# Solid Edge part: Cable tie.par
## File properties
Author: conerly
Template: Normal.par
Last saved by: jccrumbl
Revision: 38
Application: Solid Edge
Density: 1024.000 kg/m^3
Accuracy: 0.990
Material: ABS Plastic, high impact
Face Style: Red
Fill Style: ANSI34(Plastic)
Virtual Style: Red (Shiny)
Coef. of Thermal Exp: 9e-05
Thermal Conductivity: 0.2
Specific Heat: 0.0
Modulus of Elasticity: 1378951400.0
Poisson's Ratio: 0.4
Yield Stress: 31026406.5
Ultimate Stress: 0.0
Elongation: 0.0
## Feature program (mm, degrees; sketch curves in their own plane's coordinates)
sketch for "unnamed Protrusion 1" plane through (0, 0, 0) normal (0, 0, 1) x-axis (1, 0, 0)
  line (-41.7139, -4.7993) -> (-16.3139, -4.7993)
  line (-16.3139, -4.7993) -> (-16.3139, 20.6007)
  line (-16.3139, 20.6007) -> (-41.7139, 20.6007)
  line (-41.7139, 20.6007) -> (-41.7139, -4.7993)
  dimension (linear) = 41.7139
  dimension (linear) = 16.3139
extrude "unnamed Protrusion 1" add finite 3.175 along +normal
sketch for "ExtrudedProtrusion_4" #1 plane through (0, 7.9007, 0) normal (0, -1, 0) x-axis (1, 0, 0)
  circle centre (-29.0139, 22.9724) radius 12.7
sketch for "ExtrudedProtrusion_4" #2 plane through (0, 7.9007, 0) normal (0, -1, 0) x-axis (1, 0, 0)
  circle centre (-29.0139, 22.9724) radius 15.875
extrude "ExtrudedProtrusion_4" add finite 12.7 symmetric
sketch for "unnamed Protrusion 2" plane through (-34.2139, 13.1007, 3.175) normal (0, 0, 1) x-axis (0, 1, 0)
extrude "unnamed Protrusion 2" add through along +normal
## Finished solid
Body 1: solid body, 12 faces, 26 edges, 16 vertices.
  Faces by surface: plane 10, cylinder 2
  Edges by curve: line 22, circle 4
Bounding box of the edges (mm): 31.750 x 25.400 x 38.847, from (-44.8889, -4.7993, 0) to (-13.1389, 20.6007, 38.8474).
Cylindrical faces by radius (mm): R12.7 x1, R15.875 x1
Planar faces by outward normal: +x 2, +y 2, +z 1, -x 2, -y 2, -z 1
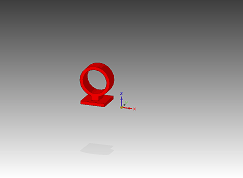
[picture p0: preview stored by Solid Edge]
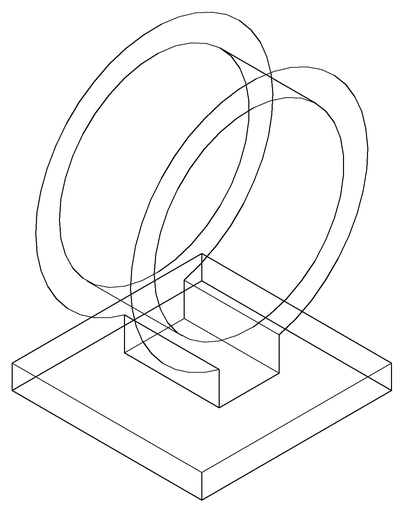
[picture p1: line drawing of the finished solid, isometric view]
